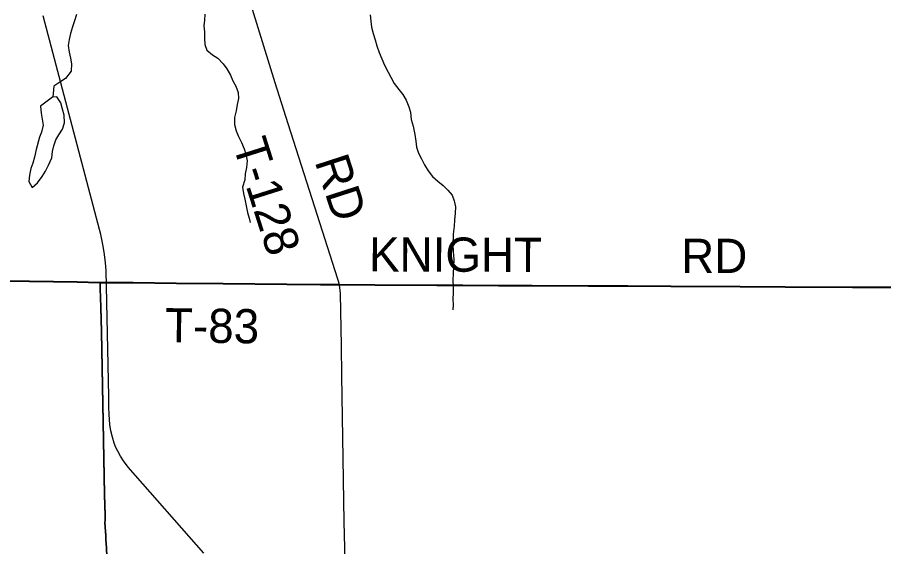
# Model space of a CAD drawing. Extents: x 0 to 34, y 0 to 22.
# Drawn here: x 4.241 to 5.679, y 16.417 to 17.296 of the extents above; entities that cross this region are included whole.
import ezdxf

# ---------------------------------------------------------------- set-up
doc = ezdxf.new("R2010")
doc.units = 0
for name, color, linetype in [('GM_X_Corporation', 7, 'Continuous'), ('GM_X_County_Road', 7, 'Continuous'), ('GM_X_Minor_Lake', 7, 'Continuous'), ('GM_X_Minor_River', 7, 'Continuous'), ('GM_X_Rail_Line', 7, 'Continuous'), ('GM_X_Township_Road', 7, 'Continuous'), ('GM_X_Township_Road_Text', 7, 'Continuous')]:
    doc.layers.add(name, color=color, linetype=linetype)

msp = doc.modelspace()

# ---------------------------------------------------------------- linework, layer by layer
at = {"layer": 'GM_X_Corporation'}
for points in [[(4.2224, 16.8579), (4.3406, 16.8565), (4.3779, 16.8556), (4.3788, 16.8556), (4.4338, 16.8551), (4.5053, 16.8543), (4.583, 16.8535), (4.6887, 16.8524), (4.7446, 16.852), (4.7762, 16.8518), (4.8348, 16.8515), (4.9374, 16.8509), (4.9809, 16.851), (5.04, 16.8505), (5.096, 16.8502), (5.1892, 16.8497), (5.2545, 16.8497), (5.326, 16.8491), (5.4411, 16.8487), (5.5157, 16.8483), (5.6276, 16.8476), (5.7178, 16.8474)], [(4.3898, 16.4019), (4.3892, 16.4237), (4.3884, 16.4267), (4.3884, 16.436), (4.3878, 16.4421), (4.3868, 16.4572), (4.3872, 16.46), (4.3871, 16.4693), (4.3862, 16.5034), (4.381, 16.7738), (4.3801, 16.8142), (4.3791, 16.8453), (4.3788, 16.8556), (4.3779, 16.8556), (4.3406, 16.8565), (4.2224, 16.8579)], [(5.7178, 16.8474), (5.6276, 16.8476), (5.5157, 16.8483), (5.4411, 16.8487), (5.326, 16.8491), (5.2545, 16.8497), (5.1892, 16.8497), (5.096, 16.8502), (5.04, 16.8505), (4.9809, 16.851), (4.9374, 16.8509), (4.8348, 16.8515), (4.7762, 16.8518), (4.7446, 16.852), (4.6887, 16.8524), (4.583, 16.8535), (4.5053, 16.8543), (4.4338, 16.8551), (4.3788, 16.8556), (4.3791, 16.8453), (4.3801, 16.8142), (4.381, 16.7738), (4.3862, 16.5034), (4.3871, 16.4693), (4.3872, 16.46), (4.3868, 16.4572), (4.3878, 16.4421), (4.3884, 16.436), (4.3884, 16.4267), (4.3892, 16.4237), (4.3898, 16.4019)]]:
    msp.add_lwpolyline(points, dxfattribs=at)
at = {"layer": 'GM_X_County_Road'}
msp.add_lwpolyline([(4.7995, 15.8093), (4.7993, 15.8152), (4.7978, 15.8649), (4.7962, 15.9395), (4.7952, 15.9798), (4.7933, 16.0606), (4.7922, 16.1072), (4.7911, 16.1507), (4.7878, 16.2936), (4.7859, 16.3743), (4.7848, 16.4147), (4.7839, 16.4582), (4.7817, 16.598), (4.7801, 16.7005), (4.7794, 16.7502), (4.7778, 16.8372), (4.7764, 16.8513)], dxfattribs=at)
at = {"layer": 'GM_X_Minor_Lake'}
for points in [[(4.2785, 17.0969), (4.2726, 17.076), (4.2697, 17.0635), (4.2671, 17.0536), (4.2641, 17.0444), (4.2619, 17.0338), (4.2605, 17.0231), (4.2662, 17.0133), (4.2749, 17.0209), (4.2828, 17.0312), (4.2881, 17.04), (4.2933, 17.0503), (4.2986, 17.0625), (4.3, 17.0728), (4.3022, 17.0823), (4.3052, 17.0922), (4.3105, 17.1006), (4.3165, 17.1101), (4.3198, 17.1204), (4.3194, 17.1334), (4.3166, 17.1432), (4.3135, 17.1535), (4.307, 17.1637), (4.2998, 17.1633)], [(4.2998, 17.1633), (4.2801, 17.1483), (4.281, 17.1365), (4.2829, 17.1267), (4.2841, 17.1164), (4.2816, 17.105), (4.2785, 17.0969)]]:
    msp.add_lwpolyline(points, dxfattribs=at)
at = {"layer": 'GM_X_Minor_River'}
for points in [[(4.3395, 17.3004), (4.3365, 17.2897), (4.3328, 17.2798), (4.3298, 17.2688), (4.3276, 17.2585), (4.3258, 17.2486), (4.3274, 17.238), (4.3297, 17.2277), (4.3313, 17.2182), (4.331, 17.206), (4.3216, 17.1942), (4.3118, 17.1881), (4.3019, 17.1811), (4.3003, 17.1633)], [(4.5526, 17.3006), (4.5523, 17.2911), (4.5512, 17.2812), (4.552, 17.2713), (4.5521, 17.261), (4.5529, 17.2504), (4.5561, 17.2409), (4.5652, 17.2334), (4.574, 17.2277), (4.5832, 17.2183), (4.5893, 17.21), (4.5951, 17.1997), (4.5993, 17.1902), (4.604, 17.1812), (4.6078, 17.1709), (4.6083, 17.1606), (4.6064, 17.1508), (4.6046, 17.1405), (4.6017, 17.1291), (4.6017, 17.1176), (4.6045, 17.1074), (4.6083, 17.0975), (4.6133, 17.0877), (4.618, 17.0774), (4.6207, 17.0683), (4.6227, 17.0573), (4.622, 17.0463), (4.6194, 17.0356), (4.6191, 17.0257), (4.615, 17.0139), (4.617, 17.0033), (4.6189, 16.9938), (4.6213, 16.9824), (4.6236, 16.9718), (4.626, 16.9619), (4.6279, 16.9547)], [(4.8269, 17.2997), (4.8281, 17.289), (4.8293, 17.2795), (4.8321, 17.2685), (4.8355, 17.2583), (4.8383, 17.2484), (4.8421, 17.2374), (4.8464, 17.2264), (4.851, 17.2162), (4.8568, 17.2048), (4.8614, 17.1961), (4.8672, 17.1859), (4.8745, 17.1756), (4.8814, 17.1673), (4.8871, 17.1582), (4.8914, 17.1472), (4.8941, 17.1381), (4.8953, 17.126), (4.8985, 17.115), (4.9012, 17.1009), (4.9028, 17.0899), (4.904, 17.08), (4.9075, 17.0698), (4.9121, 17.0607), (4.9171, 17.0508)], [(4.9171, 17.0508), (4.9233, 17.0406), (4.9306, 17.0315), (4.9394, 17.0236), (4.9485, 17.0164), (4.9558, 17.0089), (4.9631, 17.0002), (4.9666, 16.9911), (4.9685, 16.9812), (4.9682, 16.9705), (4.9672, 16.9587), (4.9665, 16.9489), (4.9647, 16.9355), (4.9644, 16.9173), (4.9649, 16.9066), (4.9657, 16.8933), (4.9654, 16.8819), (4.9651, 16.8705), (4.9644, 16.8591), (4.9649, 16.8477), (4.9646, 16.8378), (4.9643, 16.8283), (4.9647, 16.8181), (4.9644, 16.8101)]]:
    msp.add_lwpolyline(points, dxfattribs=at)
at = {"layer": 'GM_X_Rail_Line'}
msp.add_lwpolyline([(4.5512, 16.4059), (4.4256, 16.5489), (4.4179, 16.5591), (4.4127, 16.5673), (4.4081, 16.5753), (4.4051, 16.5815), (4.4023, 16.5885), (4.3993, 16.5984), (4.3967, 16.6092), (4.395, 16.6199), (4.3943, 16.628), (4.3939, 16.636), (4.3936, 16.6485), (4.3933, 16.6663), (4.3888, 16.8752), (4.3878, 16.888), (4.3861, 16.9021), (4.3839, 16.9157), (4.3802, 16.935), (4.3728, 16.9624), (4.2846, 17.2983)], dxfattribs=at)
at = {"layer": 'GM_X_Township_Road'}
for points in [[(4.7764, 16.8513), (4.7745, 16.8577), (4.7736, 16.8607), (4.7306, 16.994), (4.6912, 17.1187), (4.6695, 17.1869), (4.6317, 17.3088)], [(4.148, 16.8588), (4.1531, 16.8588), (4.1605, 16.8587), (4.1698, 16.8586), (4.2226, 16.8574), (4.3408, 16.8559), (4.3781, 16.855), (4.379, 16.855)], [(4.379, 16.855), (4.434, 16.8546), (4.5056, 16.8538), (4.5833, 16.8529), (4.6889, 16.8519), (4.7449, 16.8515), (4.7764, 16.8513)], [(4.3901, 16.4013), (4.3894, 16.4231), (4.3887, 16.4262), (4.3886, 16.4354), (4.388, 16.4415), (4.3871, 16.4567), (4.3874, 16.4594), (4.3873, 16.4687), (4.3864, 16.5029), (4.3812, 16.7732), (4.3803, 16.8136), (4.3793, 16.8447), (4.379, 16.855)], [(4.7764, 16.8513), (4.835, 16.8509), (4.9376, 16.8503), (4.9812, 16.8505), (5.0402, 16.8499), (5.0962, 16.8497), (5.1895, 16.8492), (5.2548, 16.8492), (5.3263, 16.8486), (5.4413, 16.8482), (5.5159, 16.8477), (5.6278, 16.8471), (5.718, 16.8468), (5.7709, 16.8464), (5.78, 16.8464)]]:
    msp.add_lwpolyline(points, dxfattribs=at)

# ---------------------------------------------------------------- texts
at = {"layer": 'GM_X_Township_Road_Text'}
for s, rotation, p in [('T-128', 287.6381, (4.5985, 17.0848)), ('RD', 287.9688, (4.7346, 17.0566)), ('KNIGHT', 359.8207, (4.8252, 16.8737)), ('RD', 0, (5.3433, 16.8712)), ('T-83', 359.2924, (4.4863, 16.7561))]:
    msp.add_text(s, height=0.05682, rotation=rotation, dxfattribs=at).set_placement(p)

doc.saveas('drawing.dxf')
